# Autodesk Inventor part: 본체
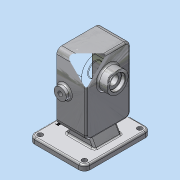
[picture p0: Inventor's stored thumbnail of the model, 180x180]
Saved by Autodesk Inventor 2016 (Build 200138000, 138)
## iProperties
Created: 2020-04
Part Number: 본체
Material: 알루미늄 6061
Document SubType Name: Modeling
Designer: Administrator
Density: 2.7 g/cm^3
Appearance: 알루미늄 - 평지
Mass: 1477.46 g
Surface Area: 817.243 cm^2
Volume: 547.208 cm^3
Author: Administrator
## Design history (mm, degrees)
sketch "스케치1"
  geometry: L1 (0, 0)-(100, 0); L2 (100, 0)-(100, 120); L3 (100, 120)-(0, 120); L4 (0, 120)-(0, 0)
  constraints: 8 end point, 2 parallel, 1 horizontal, 1 perpendicular
  dimensions: "d0" = 100 distance of L3.end L2.end; "d1" = 120 distance of L2.end L1.end
extrude "돌출1" new body sketch "스케치1" distance "d2" = 10; taper "d3" = 0 deg
node "작업 평면1"
sketch "스케치2"
  geometry: L1 (-150, 20)-(-30, 20); L2 (-30, 20)-(-30, 100); L3 (-30, 100)-(-150, 100); L4 (-150, 100)-(-150, 20); L5 (0, 0)-(-10, 0) reference; L6 (-10, 0)-(-10, 120) reference; L7 (-10, 120)-(0, 120) reference; L8 (0, 120)-(0, 0) reference; 2 further points
  constraints: 8 end point, 2 midpoint, 2 parallel, 1 horizontal, 1 horizontal alignment, 1 perpendicular
  dimensions: "d5" = 80 distance of L2.end L1.end; "d6" = 150 distance between parallel lines of L8 L4; "d7" = 120 distance between parallel lines of L2 L4
extrude "돌출2" join sketch "스케치2" distance "d8" = 53; taper "d9" = 0 deg
node "작업 평면2"
sketch "스케치3"
  geometry: L1 (-41.453, 0)-(-53, -20); L2 (0, -20)-(-11.547, 0); L3 (17, -20)-(17, -30) reference; L4 (17, -30)-(-83, -30) reference; L5 (-83, -30)-(-83, -20) reference; L6 (-83, -20)-(17, -20) reference; L7 (-53, 120)-(0, 120) reference; L8 (0, 120)-(0, 0) reference; L9 (0, 0)-(-53, 0) reference; L10 (-53, 0)-(-53, 120) reference; L11 (-53, -20)-(0, -20); L12 (17, -20)-(-83, -20) reference
  constraints: 6 end point, 4 point on line, 1 collinear
  dimensions: "d10" = 60 deg angle of L6 L2; "d11" = 60 deg angle of L6 L1; "d84" = 53 distance of L1.end L2.start; "d85" = 17 distance from line of L3 L2.start
extrude "돌출3" join sketch "스케치3" stored distance "d12" = 48; taper "d13" = 0 deg
sketch "스케치4"
  geometry: L1 (-30, 100)-(-30, 20) reference; L2 (-30, 20)-(-150, 20) reference; L3 (-150, 20)-(-150, 100) reference; L4 (-150, 100)-(-30, 100) reference; L5 (0, 0)-(-10, 0) reference; L6 (-10, 0)-(-10, 36) reference; L7 (-10, 120)-(0, 120) reference; L8 (0, 120)-(0, 0) reference; L9 (-10, 36)-(-10, 84) reference; L10 (-10, 84)-(-10, 120) reference; C1 r 19 at (-112, 60); 1 further point
  constraints: 1 centre point, 1 horizontal alignment, 1 midpoint
  dimensions: "d14" = 38 diameter of C1; "d15" = 112 distance from line of L8 C1.centre
extrude "돌출4" join sketch "스케치4" distance "d16" = 17; taper "d17" = 0 deg
sketch "스케치5"
  geometry: L1 (30, 20)-(30, 100) reference; L2 (30, 100)-(150, 100) reference; L3 (150, 100)-(150, 20) reference; L4 (150, 20)-(30, 20) reference; L5 (10, 0)-(0, 0) reference; L6 (0, 0)-(0, 120) reference; L7 (0, 120)-(10, 120) reference; L8 (10, 120)-(10, 84) reference; L9 (10, 36)-(10, 0) reference; L10 (112, 60)-(68, 60); L11 (112, 84)-(68, 84); L12 (68, 36)-(112, 36); L13 (10, 84)-(10, 36) reference; A1 r 24 centre (112, 60) between (112, 36) and (112, 84); A2 r 24 centre (68, 60) between (68, 84) and (68, 36); 2 further points
  constraints: 8 end point, 4 point on circle, 4 tangent, 2 centre point, 2 midpoint, 1 horizontal, 1 horizontal alignment, 1 parallel
  dimensions: "d18" = 24 radius of A1; "d19" = 44 distance of L10.start L10.end; "d20" = 90 distance from line of L6 point (90, 60)
extrude "돌출5" cut sketch "스케치5" distance "d21" = 29; taper "d22" = 0 deg
sketch "스케치6"
  geometry: L1 (17, 63)-(17, 101) reference; L2 (-53, 82)-(-24, 82) reference; L3 (17, 82)-(-24, 82); L4 (17, -20)-(17, -30) reference; L5 (17, -30)-(-83, -30) reference; L6 (-83, -30)-(-83, -20) reference; L7 (-83, -20)-(-53, -20) reference; L8 (-53, -20)-(-41.453, 0) reference; L9 (-41.453, 0)-(-53, 0) reference; L10 (-53, 0)-(-53, 14) reference; L11 (-53, 14)-(-24, 14) reference; L12 (-24, 14)-(-24, 106) reference; L13 (-24, 106)-(-53, 106) reference; L14 (-53, 106)-(-53, 120) reference; L15 (-53, 120)-(0, 120) reference; L16 (0, 120)-(0, 101) reference; L17 (0, 101)-(17, 101) reference; L18 (17, 101)-(17, 63) reference; L19 (17, 63)-(0, 63) reference; L20 (0, 63)-(0, 0) reference; L21 (0, 0)-(-11.547, 0) reference; L22 (-11.547, 0)-(0, -20) reference; L23 (0, -20)-(17, -20) reference; L24 (-24, 82)-(-24, 106) reference; L25 (-24, 94.5)-(-9, 94.5); L26 (-9, 94.5)-(-9, 90.5); L27 (-9, 90.5)-(9.7, 90.5); L28 (9.7, 90.5)-(9.7, 95.5); L29 (10.2, 96)-(17, 96); L30 (17, 96)-(17, 82); L31 (-24, 94.5)-(-24, 82); A1 r 0.5 centre (10.2, 95.5) between (10.2, 96) and (9.7, 95.5); 1 further point
  constraints: 16 end point, 6 perpendicular, 5 point on line, 2 collinear, 2 point on circle, 2 tangent, 1 centre point, 1 midpoint
  dimensions: "d23" = 7.3 distance of point (9.7, 96) L29.end; "d24" = 17 diameter of L27 L3; "d25" = 28 diameter of L29 L3; "d26" = 25 diameter of L25 L3; "d27" = 15 distance of L25.start L25.end; "d28" = 0.5 radius of A1
revolve "회전1" sketch "스케치6" stored, may be unused: angle "d29" = 90 deg
chamfer "모따기1" distance "d30" = 0.7; stored, may be unused: second distance "d31" = 2, angle "d32" = 30 deg
sketch "스케치7"
  geometry: L1 (68, 36)-(112, 36) reference; L2 (112, 84)-(68, 84) reference; L3 (10, 0)-(0, 0) reference; L4 (0, 0)-(0, 120) reference; L5 (0, 120)-(10, 120) reference; L6 (10, 120)-(10, 84) reference; L7 (10, 84)-(30, 84) reference; L8 (30, 84)-(30, 100) reference; L9 (30, 100)-(150, 100) reference; L10 (150, 100)-(150, 20) reference; L11 (150, 20)-(30, 20) reference; L12 (30, 20)-(30, 36) reference; L13 (30, 36)-(10, 36) reference; L14 (10, 36)-(10, 0) reference; C1 r 12.5 at (112, 60) reference; C2 r 12.5 at (68, 60); A1 r 24 centre (68, 60) between (68, 84) and (68, 36) reference; A2 r 24 centre (112, 60) between (112, 36) and (112, 84) reference
  constraints: 1 centre point, 1 coincident
  dimensions: "d33" = 25 diameter of C2
extrude "돌출6" cut sketch "스케치7" distance "d34" = 15; taper "d35" = 0 deg
sketch "스케치8"
  geometry: L1 (-83, -30)-(17, -30) reference; L2 (-53, 0)-(-53, 120) reference; C1 r 11 at (-39, 60)
  constraints: 1 centre point
  dimensions: "d36" = 22 diameter of C1; "d37" = 90 distance from line of L1 C1.centre; "d38" = 14 distance from line of L2 C1.centre
extrude "돌출7" join sketch "스케치8" distance "d39" = 8; taper "d40" = 0 deg
hole "구멍1" diameter "d43" = 8.376; stored, may be unused: countersink angle "d47" = 90 deg, drill point angle "d49" = 118 deg; dims "d41" = 10, "d42" = 10, "d44" = 20, "d45" = 4, "d46" = 2, "d48" = 27.3
sketch "스케치9"
  geometry: L1 (30, 84)-(83, 84) reference; L2 (83, 84)-(83, 36) reference; L3 (83, 36)-(30, 36) reference; L4 (30, 36)-(30, 84) reference; L5 (0, 0)-(0, 120) reference; L6 (0, 120)-(100, 120) reference; L7 (100, 120)-(100, 0) reference; L8 (100, 0)-(0, 0) reference; C1 r 4.5 at (10, 110); C2 r 4.5 at (10, 10); C3 r 4.5 at (90, 110); C4 r 4.5 at (90, 10)
  constraints: 4 centre point, 2 horizontal alignment, 2 vertical alignment
  dimensions: "d50" = 9 diameter of C1; "d51" = 9 diameter of C2; "d52" = 9 diameter of C3; "d53" = 9 diameter of C4; "d54" = 10 distance from line of L6 C1.centre; "d55" = 10 distance from line of L5 C1.centre; "d56" = 10 distance from line of L8 C4.centre; "d57" = 10 distance from line of L7 C4.centre
extrude "돌출8" cut sketch "스케치9" stored distance "d58" = 8; taper "d59" = 0 deg
sketch "스케치10"
  geometry: L1 (150, 100)-(30, 100) reference; L2 (112, 84)-(68, 84) reference; L3 (68, 36)-(112, 36) reference; L4 (30, 100)-(150, 100) reference; L5 (150, 100)-(150, 20) reference; L6 (150, 20)-(30, 20) reference; L7 (30, 20)-(30, 100) reference; L8 (10, 0)-(0, 0) reference; L9 (0, 0)-(0, 120) reference; L10 (0, 120)-(10, 120) reference; L11 (10, 120)-(10, 84) reference; L12 (10, 36)-(10, 0) reference; L13 (10, 84)-(10, 36) reference; A1 r 24 centre (68, 60) between (68, 84) and (68, 36) reference; A2 r 24 centre (112, 60) between (112, 36) and (112, 84) reference; 8 further points
  constraints: 6 horizontal alignment, 4 vertical alignment
  dimensions: "d60" = 9 distance from line of L1 point (141, 91); "d61" = 9 distance from line of L6 point (141, 29); "d62" = 9 distance from line of L5 point (141, 29); "d63" = 29 distance of point (141, 29) point (112, 29); "d64" = 44 distance of point (68, 29) point (112, 29); "d65" = 102 distance of point (39, 29) point (141, 29)
hole "구멍2" sketch "스케치10" at (141, 91), (141, 29), (112, 91), (112, 29), (68, 29), (68, 91), (39, 91), (39, 29) diameter "d66" = 4.134; stored, may be unused: countersink angle "d70" = 90 deg, drill point angle "d72" = 118 deg; dims "d67" = 10, "d68" = 4, "d69" = 2, "d71" = 12
sketch "스케치11"
  geometry: L1 (30, 84)-(83, 84) reference; L2 (83, 84)-(83, 36) reference; L3 (83, 36)-(30, 36) reference; L4 (30, 36)-(30, 84) reference; L5 (0, 0)-(0, 120) reference; L6 (0, 120)-(100, 120) reference; L7 (100, 120)-(100, 0) reference; L8 (100, 0)-(0, 0) reference; C1 r 4.5 at (90, 110) reference; C2 r 4.5 at (10, 110) reference; C3 r 4.5 at (10, 10) reference; C4 r 4.5 at (90, 10) reference; 1 further point
  constraints: 1 other
  dimensions: "d73" = 60 distance from line of L6 point (10, 60); "d74" = 10 distance from line of L5 point (10, 60)
feature "엠보싱1" sketch "스케치11" dims "d0" = 100, "d1" = 120, "d10" = 60 deg, "d11" = 60 deg, "d75" = 0.5, "d76" = 0, "d84" = 53, "d85" = 17
fillet "모깎기1" dims "d77" = 10, "d78" = 9, "d79" = 3
fillet "모깎기2" dims "d80" = 3
chamfer "모따기2" distance "d81" = 1; stored, may be unused: second distance "d82" = 2, angle "d83" = 30 deg
feature "분할1"
node "솔리드1"
mirror "대칭1"
node "절단 모서리 투영1"
node "절단 모서리 투영2"
node "절단 모서리 투영3"
node "절단 모서리 투영4"
node "절단 모서리 투영5"
node "절단 모서리 투영6"
node "절단 모서리 투영7"
node "절단 모서리 투영8"
node "절단 모서리 투영9"
other parameters: "d4" = -17
